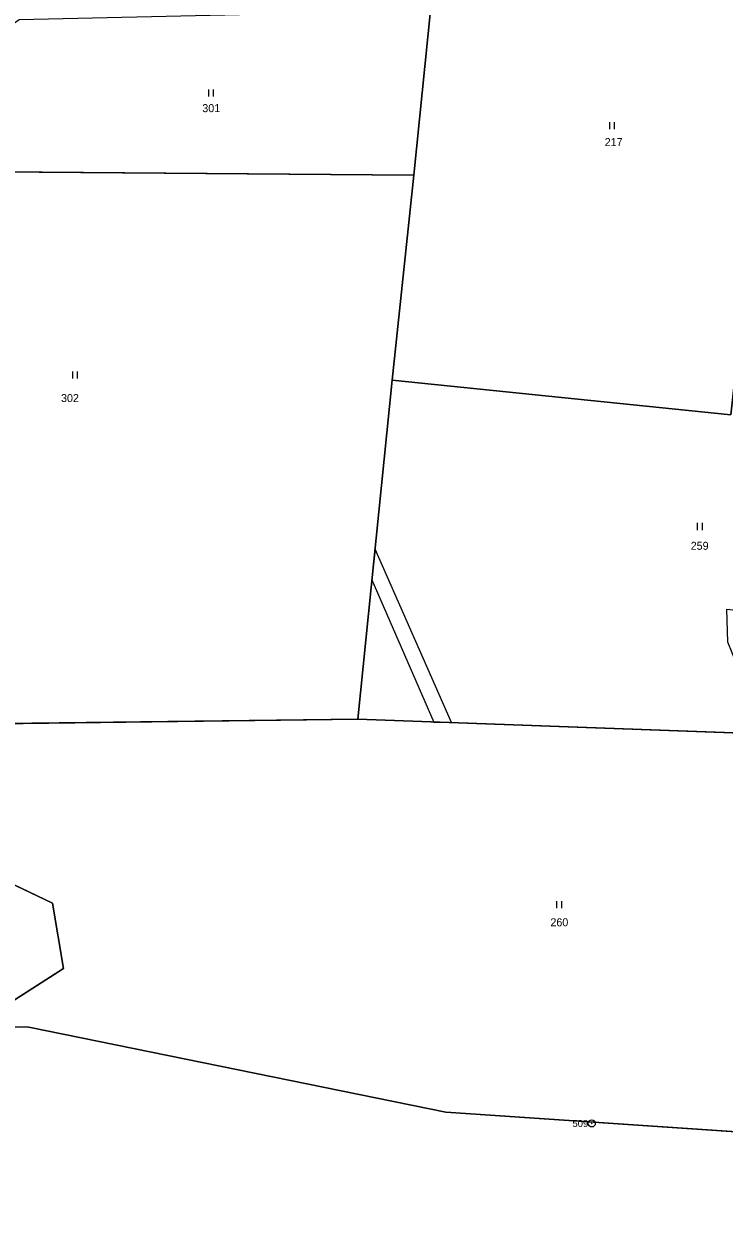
# Model space of a CAD drawing. Extents: x -689422 to -685210, y -987725 to -982160.
# Drawn here: x -686474.3 to -686325.7, y -987319.2 to -987064.7 of the extents above; entities that cross this region are included whole.
import ezdxf

# ---------------------------------------------------------------- set-up
doc = ezdxf.new("R2010")
doc.units = 0
for name, color, linetype in [('KN_Hranice_parcel', 7, 'Continuous'), ('KN_Parcelni cisla', 7, 'Continuous'), ('KN_Polygon parcely', 7, 'Continuous'), ('KN_POZEMKY_ORNA PUDA', 7, 'Continuous'), ('KN_POZEMKY_TTP', 7, 'Continuous'), ('KN_Věcná břemena k části', 7, 'Continuous'), ('KN_Značky bodu BP', 7, 'Continuous'), ('KN_Značky kultur', 7, 'Continuous')]:
    doc.layers.add(name, color=color, linetype=linetype)

msp = doc.modelspace()

# ---------------------------------------------------------------- linework, layer by layer
at = {"layer": 'KN_Hranice_parcel'}
for p, q in [((-686387.99, -987061.9), (-686391.52, -987096.84)), ((-686505.61, -987095.9), (-686391.52, -987096.84)), ((-686391.52, -987096.84), (-686396.13, -987140.43)), ((-686396.13, -987140.43), (-686403.42, -987212.43))]:
    msp.add_line(p, q, dxfattribs=at)
for points in [[(-686396.13, -987140.43), (-686324.19, -987147.76), (-686323.46, -987140.67)], [(-686403.42, -987212.43), (-686489.95, -987213.5), (-686515.47, -987206.98)], [(-686403.42, -987212.43), (-686317.77, -987215.55), (-686317.52, -987214.19)], [(-686509.16, -987227.92), (-686488.32, -987241.95), (-686468.24, -987251.5), (-686465.93, -987265.34), (-686485.19, -987277.7)], [(-686485.19, -987277.7), (-686473.26, -987277.83), (-686384.77, -987295.86), (-686312.46, -987300.78)]]:
    msp.add_lwpolyline(points, dxfattribs=at)
at = {"layer": 'KN_Polygon parcely'}
for points in [[(-686324.19, -987147.76), (-686323.46, -987140.67), (-686321.18, -987118.05), (-686294.87, -987050.2), (-686290.35, -987048.77), (-686325.83, -987031.28), (-686375.81, -987015.35), (-686381.49, -987013.89), (-686387.99, -987061.9), (-686391.52, -987096.84), (-686396.13, -987140.43)], [(-686505.61, -987095.9), (-686391.52, -987096.84), (-686387.99, -987061.9), (-686475.36, -987063.89), (-686488.8, -987073.41)], [(-686526.61, -987192.87), (-686515.47, -987206.98), (-686489.95, -987213.5), (-686403.42, -987212.43), (-686396.13, -987140.43), (-686391.52, -987096.84), (-686505.61, -987095.9), (-686508.36, -987096.03), (-686550.73, -987149.79), (-686538.94, -987169.48)], [(-686403.42, -987212.43), (-686317.77, -987215.55), (-686317.52, -987214.19), (-686324.83, -987196.04), (-686325.09, -987189.05), (-686293.77, -987192.46), (-686264.93, -987201.68), (-686255.05, -987167.51), (-686283.32, -987157.62), (-686321.55, -987148.81), (-686321, -987146.25), (-686320.39, -987143.11), (-686318.98, -987127.62), (-686323.46, -987140.67), (-686324.19, -987147.76), (-686396.13, -987140.43)], [(-686509.16, -987227.92), (-686508.53, -987246.57), (-686499.63, -987264.4), (-686497.84, -987267.98), (-686485.19, -987277.7), (-686465.93, -987265.34), (-686468.24, -987251.5), (-686488.32, -987241.95)], [(-686280.17, -987421.73), (-686278.21, -987417.3), (-686279.46, -987417.1), (-686310.05, -987412.68), (-686333.82, -987405.66), (-686312.46, -987300.78), (-686384.77, -987295.86), (-686473.26, -987277.83), (-686485.19, -987277.7), (-686497.84, -987267.98), (-686522.78, -987288.63), (-686567.63, -987359.69), (-686536.52, -987352.9), (-686470.17, -987361.65), (-686353.52, -987404.88), (-686346.65, -987407.07), (-686330.04, -987412.47)]]:
    msp.add_lwpolyline(points, close=True, dxfattribs=at)
msp.add_lwpolyline([(-686317.77, -987215.55), (-686403.42, -987212.43), (-686489.95, -987213.5), (-686515.47, -987206.98), (-686509.36, -987221.94), (-686509.16, -987227.92), (-686488.32, -987241.95), (-686468.24, -987251.5), (-686465.93, -987265.34), (-686485.19, -987277.7), (-686473.26, -987277.83), (-686384.77, -987295.86), (-686312.46, -987300.78)], dxfattribs=at)
at = {"layer": 'KN_POZEMKY_ORNA PUDA'}
for p, q in [((-686485.19, -987277.7), (-686473.26, -987277.83)), ((-686473.26, -987277.83), (-686384.77, -987295.86)), ((-686384.77, -987295.86), (-686312.46, -987300.78))]:
    msp.add_line(p, q, dxfattribs=at)
at = {"layer": 'KN_POZEMKY_TTP'}
for p, q in [((-686391.52, -987096.84), (-686387.99, -987061.9)), ((-686387.99, -987061.9), (-686391.52, -987096.84)), ((-686505.61, -987095.9), (-686391.52, -987096.84)), ((-686391.52, -987096.84), (-686505.61, -987095.9)), ((-686396.13, -987140.43), (-686391.52, -987096.84)), ((-686391.52, -987096.84), (-686396.13, -987140.43)), ((-686403.42, -987212.43), (-686396.13, -987140.43)), ((-686396.13, -987140.43), (-686403.42, -987212.43)), ((-686324.19, -987147.76), (-686396.13, -987140.43)), ((-686396.13, -987140.43), (-686324.19, -987147.76)), ((-686489.95, -987213.5), (-686403.42, -987212.43)), ((-686403.42, -987212.43), (-686489.95, -987213.5)), ((-686403.42, -987212.43), (-686317.77, -987215.55)), ((-686317.77, -987215.55), (-686403.42, -987212.43)), ((-686468.24, -987251.5), (-686488.32, -987241.95)), ((-686488.32, -987241.95), (-686468.24, -987251.5)), ((-686465.93, -987265.34), (-686468.24, -987251.5)), ((-686468.24, -987251.5), (-686465.93, -987265.34)), ((-686485.19, -987277.7), (-686465.93, -987265.34)), ((-686465.93, -987265.34), (-686485.19, -987277.7)), ((-686473.26, -987277.83), (-686485.19, -987277.7)), ((-686384.77, -987295.86), (-686473.26, -987277.83)), ((-686312.46, -987300.78), (-686384.77, -987295.86))]:
    msp.add_line(p, q, dxfattribs=at)
at = {"layer": 'KN_Věcná břemena k části'}
msp.add_lwpolyline([(-686387.26, -987213.02), (-686383.56, -987213.15), (-686399.76, -987176.28), (-686400.42, -987182.84)], close=True, dxfattribs=at)
at = {"layer": 'KN_Značky bodu BP'}
for radius in [0.75, 0.03]:
    msp.add_circle((-686353.75, -987298.29), radius, dxfattribs=at)
at = {"layer": 'KN_Značky kultur'}
for p, q in [((-686435.09, -987080.13), (-686435.09, -987078.63)), ((-686434.09, -987080.13), (-686434.09, -987078.63)), ((-686349.89, -987087.1), (-686349.89, -987085.6)), ((-686348.89, -987087.1), (-686348.89, -987085.6)), ((-686463.95, -987140.04), (-686463.95, -987138.54)), ((-686462.95, -987140.04), (-686462.95, -987138.54)), ((-686331.27, -987172.23), (-686331.27, -987170.73)), ((-686330.27, -987172.23), (-686330.27, -987170.73)), ((-686361.14, -987252.59), (-686361.14, -987251.09)), ((-686360.14, -987252.59), (-686360.14, -987251.09))]:
    msp.add_line(p, q, dxfattribs=at)

# ---------------------------------------------------------------- texts
at = {"layer": 'KN_Parcelni cisla'}
for s, p in [('301', (-686436.44, -987083.47)), ('217', (-686351, -987090.67)), ('302', (-686466.44, -987145.05)), ('259', (-686332.74, -987176.43)), ('260', (-686362.53, -987256.41))]:
    msp.add_text(s, height=1.7, dxfattribs=at).set_placement(p)
at = {"layer": 'KN_Značky bodu BP'}
msp.add_text('509', height=1.5, dxfattribs=at).set_placement((-686357.85, -987299.04))

doc.saveas('drawing.dxf')
